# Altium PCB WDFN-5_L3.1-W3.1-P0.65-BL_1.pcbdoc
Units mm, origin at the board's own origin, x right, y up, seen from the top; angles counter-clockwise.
Board outline 16.58 x 16.67 mm, 2 copper layers (Top Layer, Bottom Layer), stack 0 mm thick; 1 components, 0 nets, 5 pads, 0 vias.
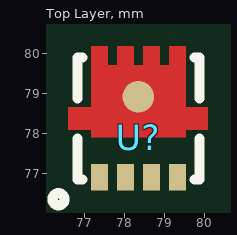
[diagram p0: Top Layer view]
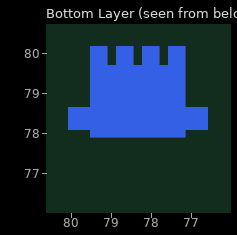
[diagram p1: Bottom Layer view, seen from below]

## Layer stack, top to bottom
Top Layer: signal copper (thickness not stored)
Bottom Layer: signal copper (thickness not stored)

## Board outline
86.43,69.85 69.85,69.85 69.85,86.52 86.43,86.52

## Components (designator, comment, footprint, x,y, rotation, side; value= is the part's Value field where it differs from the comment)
U? "" WDFN-5_L3.1-W3.1-P0.65-BL_1 78.35,77.635 r0 top

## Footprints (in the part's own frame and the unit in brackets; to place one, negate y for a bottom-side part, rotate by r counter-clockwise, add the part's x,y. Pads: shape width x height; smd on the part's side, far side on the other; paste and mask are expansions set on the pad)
WDFN-5_L3.1-W3.1-P0.65-BL_1 [mm]
  rect 0.42x0.66 smd: 1(-0.975,-0.735) 2(-0.325,-0.735) 3(0.325,-0.735) 4(0.975,-0.735)
  round 0.788 smd: 5(-0.004,1.277)
  Top Layer region: 1.185,0.45 1.185,0.27 -1.185,0.27 -1.185,0.45 -1.75,0.45 -1.75,1.02 -1.185,1.02 -1.185,2.535 -0.765,2.535 -0.765,2.065 -0.535,2.065 -0.535,2.535 -0.115,2.535 -0.115,2.065 0.115,2.065 0.115,2.535 0.535,2.535 0.535,2.065 0.765,2.065 0.765,2.535 1.185,2.535 1.185,1.02 1.73,1.02 1.73,0.45
  Bottom Layer region: 1.185,0.45 1.185,0.27 -1.185,0.27 -1.185,0.45 -1.75,0.45 -1.75,1.02 -1.185,1.02 -1.185,2.535 -0.765,2.535 -0.765,2.065 -0.535,2.065 -0.535,2.535 -0.115,2.535 -0.115,2.065 0.115,2.065 0.115,2.535 0.535,2.535 0.535,2.065 0.765,2.065 0.765,2.535 1.185,2.535 1.185,1.02 1.73,1.02 1.73,0.45
  Multi-Layer region: 1.185,0.45 1.185,0.27 -1.185,0.27 -1.185,0.45 -1.75,0.45 -1.75,1.02 -1.185,1.02 -1.185,2.535 -0.765,2.535 -0.765,2.065 -0.535,2.065 -0.535,2.535 -0.115,2.535 -0.115,2.065 0.115,2.065 0.115,2.535 0.535,2.535 0.535,2.065 0.765,2.065 0.765,2.535 1.185,2.535 1.185,1.02 1.73,1.02 1.73,0.45
  silkscreen extent -2.15,-1.43 1.52,2.26

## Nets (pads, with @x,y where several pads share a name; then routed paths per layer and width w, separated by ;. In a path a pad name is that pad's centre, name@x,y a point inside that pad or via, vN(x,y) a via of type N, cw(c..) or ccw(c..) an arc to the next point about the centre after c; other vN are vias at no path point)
pads on no net: U?.1 U?.2 U?.3 U?.4 U?.5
